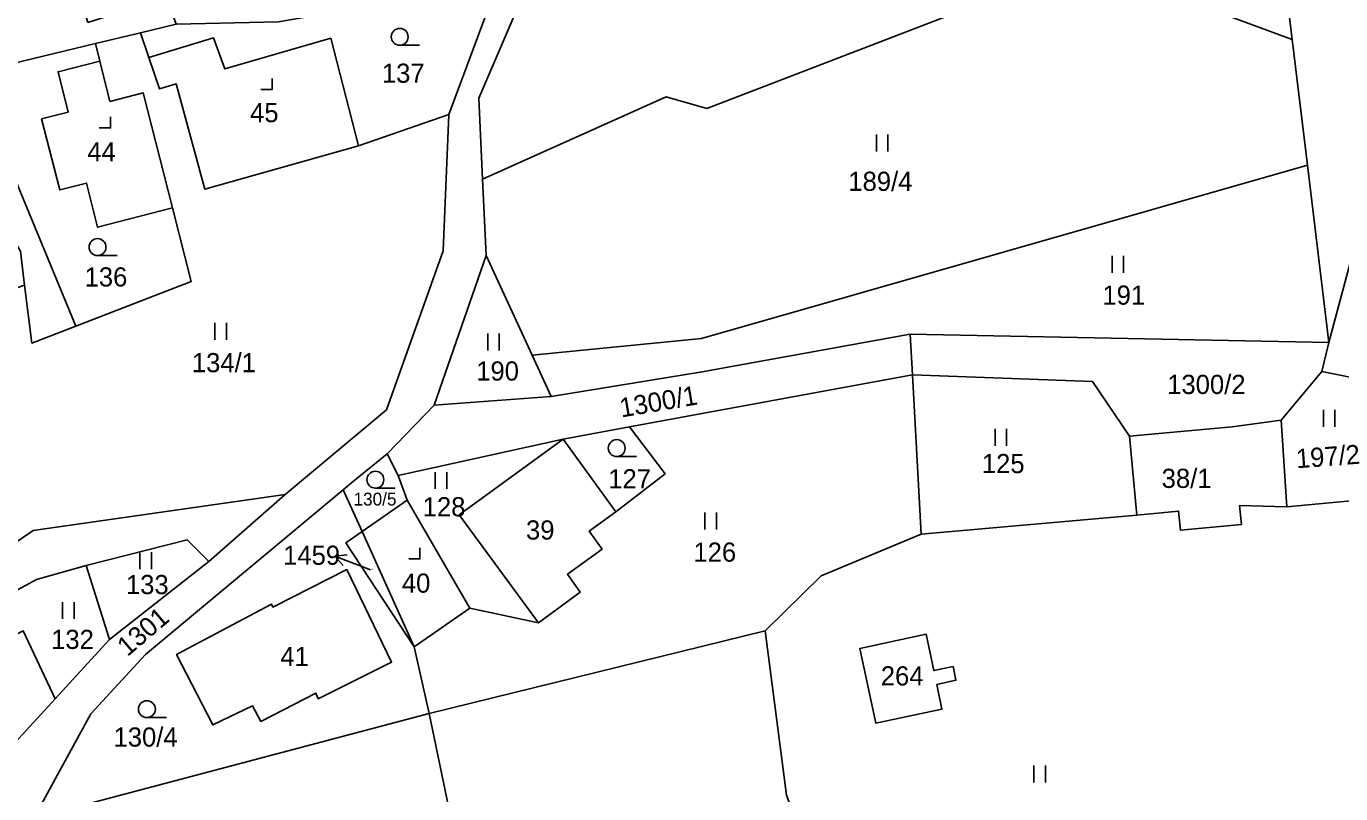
# Model space of a CAD drawing. Extents: x -588699 to -585793, y -1060280 to -1056731.
# Drawn here: x -588042.9 to -587926.2, y -1058283.1 to -1058215 of the extents above; entities that cross this region are included whole.
import ezdxf

# ---------------------------------------------------------------- set-up
doc = ezdxf.new("R2010")
doc.units = 0
for name, color, linetype in [('Druh pozemku', 7, 'Continuous'), ('Lesy', 7, 'Continuous'), ('Parcela nároku', 7, 'Continuous'), ('Parcelní číslo', 7, 'Continuous')]:
    doc.layers.add(name, color=color, linetype=linetype)

msp = doc.modelspace()

# ---------------------------------------------------------------- linework, layer by layer
at = {"layer": 'Druh pozemku'}
for p, q in [((-588008.02, -1058216.73), (-588009.77, -1058216.73)), ((-587967.46, -1058224.65), (-587967.46, -1058226.15)), ((-587966.44, -1058226.15), (-587966.44, -1058224.65)), ((-588034.84, -1058235.37), (-588036.59, -1058235.37)), ((-587946.54, -1058235.4), (-587946.54, -1058236.9)), ((-587945.52, -1058236.9), (-587945.52, -1058235.4)), ((-588026.17, -1058241.34), (-588026.17, -1058242.84)), ((-588025.15, -1058242.84), (-588025.15, -1058241.34)), ((-588001.95, -1058242.29), (-588001.95, -1058243.79)), ((-588000.93, -1058243.79), (-588000.93, -1058242.29)), ((-587927.78, -1058249.05), (-587927.78, -1058250.55)), ((-587926.76, -1058250.55), (-587926.76, -1058249.05)), ((-587956.92, -1058250.74), (-587956.92, -1058252.24)), ((-587955.9, -1058252.24), (-587955.9, -1058250.74)), ((-587988.76, -1058253.2), (-587990.51, -1058253.2)), ((-588006.63, -1058254.57), (-588006.63, -1058256.07)), ((-588005.6, -1058256.07), (-588005.6, -1058254.57)), ((-588010.18, -1058256), (-588011.93, -1058256)), ((-587982.68, -1058258.17), (-587982.68, -1058259.67)), ((-587981.66, -1058259.67), (-587981.66, -1058258.17)), ((-588032.83, -1058261.69), (-588032.83, -1058263.19)), ((-588031.81, -1058263.19), (-588031.81, -1058261.69)), ((-588039.69, -1058266.1), (-588039.69, -1058267.6)), ((-588038.67, -1058267.6), (-588038.67, -1058266.1)), ((-588030.46, -1058276.35), (-588032.21, -1058276.35)), ((-587953.49, -1058280.59), (-587953.49, -1058282.09)), ((-587952.46, -1058282.09), (-587952.46, -1058280.59))]:
    msp.add_line(p, q, dxfattribs=at)
for points in [[(-588022.1, -1058220.66), (-588021.1, -1058220.66), (-588021.1, -1058219.66)], [(-588036.44, -1058224.06), (-588035.44, -1058224.06), (-588035.44, -1058223.06)], [(-588008.97, -1058262.28), (-588007.97, -1058262.28), (-588007.97, -1058261.28)]]:
    msp.add_lwpolyline(points, dxfattribs=at)
for centre in [(-588009.77, -1058215.98), (-588036.59, -1058234.62), (-587990.51, -1058252.45), (-588011.93, -1058255.25), (-588032.21, -1058275.6)]:
    msp.add_circle(centre, 0.75, dxfattribs=at)
at = {"layer": 'Lesy'}
msp.add_line((-588042.29, -1058259.76), (-588051.6, -1058266.1), dxfattribs=at)
msp.add_lwpolyline([(-588042.39, -1058313.12), (-588042.77, -1058294.96), (-588042.26, -1058285.27), (-588047.55, -1058287.8), (-588062.03, -1058292.92), (-588064.18, -1058290.52), (-588070.77, -1058279.03), (-588058.25, -1058271.46), (-588050.83, -1058268.88), (-588042, -1058264.1), (-588037.6, -1058262.86), (-588028.63, -1058260.57), (-588026.72, -1058262.49), (-588019.94, -1058256.55), (-588042.29, -1058259.76)], dxfattribs=at)
at = {"layer": 'Parcela nároku'}
for points in [[(-587937.19, -1058175.57), (-587923.93, -1058183.49), (-587926.7, -1058188.48), (-587898.86, -1058184.66), (-587888.94, -1058185.21), (-587884.21, -1058183.4), (-587886.93, -1058176.48), (-587883.4, -1058175.08), (-587886.16, -1058167.86), (-587887.26, -1058165.09), (-587878.46, -1058165.39), (-587874.84, -1058186.24), (-587933.04, -1058195.62), (-587930.55, -1058216.22), (-587939.22, -1058213.03), (-587944.64, -1058202.99)], [(-587878.46, -1058165.39), (-587852.6, -1058169.68), (-587842.96, -1058169.39), (-587845.87, -1058217.7), (-587852.17, -1058218.46), (-587874.99, -1058223.36), (-587893.08, -1058224.69), (-587921.7, -1058222.21), (-587922.75, -1058226.1), (-587927.3, -1058243.08), (-587929.2, -1058227.37), (-587930.55, -1058216.22), (-587933.04, -1058195.62), (-587874.84, -1058186.24)], [(-587962.1, -1058205.72), (-587997.97, -1058210.3), (-588002.76, -1058221.42), (-588002.42, -1058228.61), (-587986.11, -1058221.3), (-587982.5, -1058222.32), (-587955.25, -1058211.83), (-587939.22, -1058213.03), (-587944.64, -1058202.99), (-587937.19, -1058175.57), (-587936.49, -1058173), (-587953.79, -1058176.32), (-587955.95, -1058177.06), (-587953.8, -1058182.5), (-587967.62, -1058186.12)], [(-588037.44, -1058214.7), (-588038.19, -1058212.33), (-588045.35, -1058214.64), (-588048.39, -1058205.39), (-588058.38, -1058208.56), (-588053.92, -1058217.06), (-588052.23, -1058220.29), (-588047.8, -1058219.23), (-588036.77, -1058216.58), (-588032.79, -1058215.62), (-588029.61, -1058214.86), (-588030.46, -1058212.46)], [(-588032.79, -1058215.62), (-588029.61, -1058214.86), (-588020.54, -1058214.66), (-588001.08, -1058211.26), (-588005.42, -1058222.88), (-588013.42, -1058225.65), (-588015.88, -1058216.1), (-588025.29, -1058218.83), (-588026.29, -1058216.07), (-588032.03, -1058217.82)], [(-587939.22, -1058213.03), (-587955.25, -1058211.83), (-587982.5, -1058222.32), (-587986.11, -1058221.3), (-588002.42, -1058228.61), (-588002.11, -1058235.37), (-587998.02, -1058244.21), (-587982.98, -1058242.73), (-587929.2, -1058227.37), (-587930.55, -1058216.22)], [(-588032.03, -1058217.82), (-588032.79, -1058215.62), (-588036.77, -1058216.58), (-588036.38, -1058218.14), (-588035.49, -1058221.71), (-588032.53, -1058220.95), (-588029.94, -1058231.14), (-588028.28, -1058237.68), (-588038.53, -1058241.64), (-588042.41, -1058243.13), (-588043.06, -1058238.01), (-588055.57, -1058242.31), (-588058.21, -1058243.22), (-588051.99, -1058264.75), (-588051.6, -1058266.1), (-588042.29, -1058259.76), (-588019.94, -1058256.55), (-588010.93, -1058249.05), (-588005.9, -1058234.96), (-588005.42, -1058222.88), (-588013.42, -1058225.65), (-588027.07, -1058229.5), (-588029.61, -1058220.15), (-588031.08, -1058220.59)], [(-588015.88, -1058216.1), (-588025.29, -1058218.83), (-588026.29, -1058216.07), (-588032.03, -1058217.82), (-588031.08, -1058220.59), (-588029.61, -1058220.15), (-588027.07, -1058229.5), (-588013.42, -1058225.65)], [(-588039.93, -1058229.55), (-588041.56, -1058223.26), (-588039.19, -1058222.65), (-588040.1, -1058219.07), (-588036.38, -1058218.14), (-588036.77, -1058216.58), (-588047.8, -1058219.23), (-588038.53, -1058241.64), (-588028.28, -1058237.68), (-588029.94, -1058231.14), (-588036.59, -1058232.86), (-588037.58, -1058228.95)], [(-588029.94, -1058231.14), (-588032.53, -1058220.95), (-588035.49, -1058221.71), (-588036.38, -1058218.14), (-588040.1, -1058219.07), (-588039.19, -1058222.65), (-588041.56, -1058223.26), (-588039.93, -1058229.55), (-588037.58, -1058228.95), (-588036.59, -1058232.86)], [(-588047.8, -1058219.23), (-588052.23, -1058220.29), (-588046.46, -1058229.93), (-588045.41, -1058231.69), (-588043.44, -1058234.98), (-588043.06, -1058238.01), (-588042.41, -1058243.13), (-588038.53, -1058241.64)], [(-587908.69, -1058227.46), (-587922.75, -1058226.1), (-587927.3, -1058243.08), (-587927.92, -1058245.65), (-587923.51, -1058246.54), (-587911.37, -1058248.97), (-587911.37, -1058241.77)], [(-587998.02, -1058244.21), (-587982.98, -1058242.73), (-587929.2, -1058227.37), (-587927.3, -1058243.08), (-587964.45, -1058242.34), (-587982.93, -1058245.68), (-587996.33, -1058247.86)], [(-588002.11, -1058235.37), (-588006.72, -1058248.64), (-587996.33, -1058247.86), (-587998.02, -1058244.21)], [(-587982.93, -1058245.68), (-587964.45, -1058242.34), (-587964.26, -1058245.94), (-587989.36, -1058250.57), (-587995.26, -1058251.66), (-588009.9, -1058254.89), (-588010.89, -1058252.97), (-588006.72, -1058248.64), (-587996.33, -1058247.86)], [(-587927.3, -1058243.08), (-587964.45, -1058242.34), (-587964.26, -1058245.94), (-587948.29, -1058246.54), (-587945.01, -1058251.4), (-587935.89, -1058250.57), (-587931.54, -1058249.97), (-587927.92, -1058245.65)], [(-587927.92, -1058245.65), (-587923.51, -1058246.54), (-587922.52, -1058257.09), (-587925.02, -1058257.11), (-587931.04, -1058257.66), (-587931.54, -1058249.97)], [(-587994.89, -1058263.63), (-587991.81, -1058261.41), (-587992.96, -1058259.82), (-587990.58, -1058258.1), (-587986.22, -1058254.73), (-587989.36, -1058250.57), (-587964.26, -1058245.94), (-587963.49, -1058260.08), (-587972.37, -1058263.79), (-587977.33, -1058268.66), (-588007.16, -1058275.99), (-588008.5, -1058270.06), (-588003.56, -1058266.65), (-587997.46, -1058267.94), (-587993.75, -1058265.22)], [(-587945.01, -1058251.4), (-587944.35, -1058258.4), (-587963.49, -1058260.08), (-587964.26, -1058245.94), (-587948.29, -1058246.54)], [(-587935.06, -1058259.21), (-587935.22, -1058257.53), (-587931.04, -1058257.66), (-587931.54, -1058249.97), (-587935.89, -1058250.57), (-587945.01, -1058251.4), (-587944.35, -1058258.4), (-587940.64, -1058258.04), (-587940.48, -1058259.73)], [(-587995.26, -1058251.66), (-587989.36, -1058250.57), (-587986.22, -1058254.73), (-587990.58, -1058258.1)], [(-587997.46, -1058267.94), (-588004.5, -1058258.38), (-587995.26, -1058251.66), (-588009.9, -1058254.89), (-588009.1, -1058257.07), (-588003.56, -1058266.65)], [(-587995.26, -1058251.66), (-588004.5, -1058258.38), (-587997.46, -1058267.94), (-587993.75, -1058265.22), (-587994.89, -1058263.63), (-587991.81, -1058261.41), (-587992.96, -1058259.82), (-587990.58, -1058258.1)], [(-588009.9, -1058254.89), (-588010.89, -1058252.97), (-588013.86, -1058255.37), (-588014.78, -1058256.14), (-588013.11, -1058259.85), (-588009.1, -1058257.07)], [(-588008.5, -1058270.06), (-588007.16, -1058275.99), (-588042.26, -1058285.27), (-588037.18, -1058276.01), (-588032.33, -1058270.74), (-588014.78, -1058256.14), (-588013.11, -1058259.85), (-588014.55, -1058260.85)], [(-588092.09, -1058297.15), (-588089.42, -1058294.34), (-588088.04, -1058292.89), (-588092.66, -1058287.94), (-588085.06, -1058285.41), (-588060.5, -1058268.79), (-588051.6, -1058266.1), (-588042.29, -1058259.76), (-588019.94, -1058256.55), (-588026.72, -1058262.49), (-588028.63, -1058260.57), (-588037.6, -1058262.86), (-588042, -1058264.1), (-588050.83, -1058268.88), (-588058.25, -1058271.46), (-588070.77, -1058279.03), (-588076.72, -1058283.98), (-588088.99, -1058299.83)], [(-588009.1, -1058257.07), (-588003.56, -1058266.65), (-588008.5, -1058270.06), (-588013.11, -1058259.85)], [(-587940.64, -1058258.04), (-587940.48, -1058259.73), (-587935.06, -1058259.21), (-587935.22, -1058257.53), (-587931.04, -1058257.66), (-587925.02, -1058257.11), (-587924.44, -1058297.23), (-587916.71, -1058316.19), (-587936.92, -1058313.67), (-587941.04, -1058292.83), (-587941.51, -1058290), (-587970.94, -1058295.5), (-587975.43, -1058283.23), (-587977.33, -1058268.66), (-587972.37, -1058263.79), (-587963.49, -1058260.08), (-587944.35, -1058258.4)], [(-588028.63, -1058260.57), (-588037.6, -1058262.86), (-588035.53, -1058269.41), (-588026.72, -1058262.49)], [(-588008.5, -1058270.06), (-588013.11, -1058259.85), (-588014.55, -1058260.85)], [(-588050.83, -1058268.88), (-588058.25, -1058271.46), (-588056.88, -1058275.65), (-588055.94, -1058275.17), (-588047.85, -1058271.04), (-588043.18, -1058268.66), (-588040.35, -1058274.68), (-588035.53, -1058269.41), (-588037.6, -1058262.86), (-588042, -1058264.1)], [(-588029.57, -1058270.74), (-588021.15, -1058266.3), (-588021.03, -1058266.54), (-588014.46, -1058263.22), (-588010.49, -1058271.43), (-588017.02, -1058274.67), (-588017.22, -1058274.17), (-588022.09, -1058276.69), (-588022.84, -1058275.29), (-588026.36, -1058277)], [(-588017.22, -1058274.17), (-588022.09, -1058276.69), (-588022.84, -1058275.29), (-588026.36, -1058277), (-588029.57, -1058270.74), (-588021.15, -1058266.3), (-588021.03, -1058266.54), (-588014.46, -1058263.22), (-588010.49, -1058271.43), (-588017.02, -1058274.67)], [(-588040.35, -1058274.68), (-588043.18, -1058268.66), (-588047.85, -1058271.04), (-588055.94, -1058275.17), (-588052.74, -1058281.38), (-588052.03, -1058282.76), (-588048.73, -1058281.06), (-588043.9, -1058278.57)], [(-587977.33, -1058268.66), (-588007.16, -1058275.99), (-588005.45, -1058284.22), (-588001.57, -1058304.59), (-587982.74, -1058314.02), (-587980.69, -1058313.21), (-587967.75, -1058308.09), (-587969.63, -1058298.48), (-587970.94, -1058295.5), (-587975.43, -1058283.23)], [(-587960.4, -1058273.03), (-587960.66, -1058271.82), (-587962.36, -1058272.18), (-587963.05, -1058268.96), (-587968.92, -1058270.21), (-587967.52, -1058276.84), (-587961.64, -1058275.6), (-587962.1, -1058273.42)], [(-587962.1, -1058273.42), (-587960.4, -1058273.03), (-587960.66, -1058271.82), (-587962.36, -1058272.18), (-587963.05, -1058268.96), (-587968.92, -1058270.21), (-587967.52, -1058276.84), (-587961.64, -1058275.6)], [(-588007.16, -1058275.99), (-588042.26, -1058285.27), (-588042.77, -1058294.96), (-588005.45, -1058284.22)]]:
    msp.add_lwpolyline(points, close=True, dxfattribs=at)
msp.add_lwpolyline([(-588043.9, -1058278.57), (-588040.35, -1058274.68), (-588035.53, -1058269.41), (-588026.72, -1058262.49), (-588019.94, -1058256.55), (-588010.93, -1058249.05), (-588005.9, -1058234.96), (-588005.42, -1058222.88), (-588001.08, -1058211.26), (-587990.55, -1058189.72), (-587985.91, -1058188.6), (-587997.97, -1058210.3), (-588002.76, -1058221.42), (-588002.42, -1058228.61), (-588002.11, -1058235.37), (-588006.72, -1058248.64), (-588010.89, -1058252.97), (-588013.86, -1058255.37), (-588014.78, -1058256.14), (-588032.33, -1058270.74), (-588037.18, -1058276.01), (-588042.26, -1058285.27)], dxfattribs=at)
at = {"layer": 'Parcelní číslo'}
for p, q in [((-588012.74, -1058263.1), (-588015.54, -1058262.04)), ((-588012.36, -1058263.25), (-588012.74, -1058263.1))]:
    msp.add_line(p, q, dxfattribs=at)
msp.add_lwpolyline([(-588014.79, -1058262.86), (-588015.54, -1058262.04), (-588014.43, -1058261.92)], dxfattribs=at)

# ---------------------------------------------------------------- texts
at = {"layer": 'Parcela nároku'}
for s, height, p in [('137', 1.7, (-588011.35, -1058220.05)), ('45', 1.7, (-588023.05, -1058223.55)), ('44', 1.7, (-588037.5, -1058227.02)), ('189/4', 1.7, (-587969.95, -1058229.64)), ('136', 1.7, (-588037.74, -1058238.12)), ('191', 1.7, (-587947.4, -1058239.73)), ('134/1', 1.7, (-588028.22, -1058245.72)), ('190', 1.7, (-588002.98, -1058246.46)), ('1300/2', 1.7, (-587941.65, -1058247.65)), ('125', 1.7, (-587958.1, -1058254.67)), ('127', 1.7, (-587991.26, -1058256.02)), ('38/1', 1.7, (-587942.14, -1058255.98)), ('130/5', 1.14, (-588013.87, -1058257.54)), ('128', 1.7, (-588007.73, -1058258.5)), ('39', 1.7, (-587998.56, -1058260.56)), ('126', 1.7, (-587983.7, -1058262.52)), ('1459', 0.1, (-588012.48, -1058263.25)), ('133', 1.7, (-588034.07, -1058265.4)), ('40', 1.7, (-588009.58, -1058265.27)), ('132', 1.7, (-588040.71, -1058270.26)), ('41', 1.7, (-588020.37, -1058271.78)), ('264', 1.7, (-587967.07, -1058273.5)), ('130/4', 1.7, (-588035.17, -1058278.92))]:
    msp.add_text(s, height=height, dxfattribs=at).set_placement(p)
for s, rotation, p in [('1300/1', 9.7299, (-587990.1, -1058249.74)), ('197/2', 4.1596, (-587930.16, -1058254.24)), ('1301', 40.3945, (-588033.94, -1058270.99))]:
    msp.add_text(s, height=1.7, rotation=rotation, dxfattribs=at).set_placement(p)
at = {"layer": 'Parcelní číslo'}
msp.add_text('1459', height=1.7, dxfattribs=at).set_placement((-588020.12, -1058262.8))

doc.saveas('drawing.dxf')
